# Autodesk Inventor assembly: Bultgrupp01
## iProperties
Author: Tobben
Created: 2001-12
Part Number: Bultgrupp01
Document SubType Name: Assembly
Designer: Tobben
Control State: 0
Master: False
Checked Out: False
PropertySet Name: Design Tracking Control
Shininess: 64.0
Angle Display Precision: 2
Document Length Units: 11269
Document Angle Units: 11283
Document Time Units: 11279
Document Mass Units: 11290
Document Length Units Precision: 3
Document Angle Units Precision: 2
Compacted: False
PropertySet Name: _Private Model Information
Density: 0.0
Volumn: 0.0
Area: 0.0
PropertySet Name: Model Information
